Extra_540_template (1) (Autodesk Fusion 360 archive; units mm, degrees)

design "Extra_540_template" references "Extra_540_rear_tags"
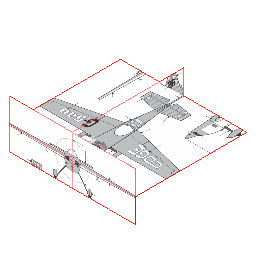
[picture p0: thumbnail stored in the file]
canvas "Canvas1"
canvas "Canvas2"
canvas "Canvas3"
component_insert "Component Insert"
ground "Ground4"

design "Extra_540_freeform_Undercarriage"
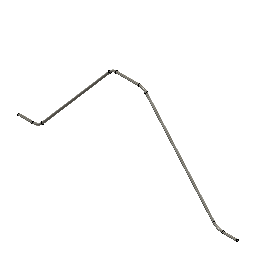
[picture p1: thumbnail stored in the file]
base_feature "Base Feature"
sketch "Path (1)" plane through (0, 0, -48.1) normal (0, 0, 1) x axis (1, 0, 0)
  dimension "d165" = 5
  dimension "d166" = 4
  dimension "d178" = 0
  dimension "d179" = 0
  dimension "d180" = 0
  dimension "d181" = 0
  dimension "d190" = 0
  dimension "d191" = 0
  dimension "d192" = 0
  dimension "d193" = 0
sketch "Profile" plane through (0, 0, 0) normal (1, 0, 0) x axis (0, 0, -1)
  circle C1 centre (47.7, -10.2807) radius 0.375
  dimension "d167" diameter C1 = 0.75
sweep "Sweep1" sketch "Profile" TwistAngle 0 TaperAngle 0

design "Propeller_3_x_1"
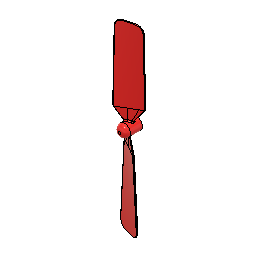
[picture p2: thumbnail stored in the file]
sketch "Sketch1" plane through (0, 0, 0) normal (1, 0, 0) x axis (0, 0, -1)
  dimension "d1" = 1
  dimension "d2" = 2.5
  dimension "d3" = 2
  dimension "d5" = 7
  dimension "d6" = 115
  dimension "d7" = 1.5
revolve "Revolve1" sketch "Sketch1" AlongAngle 360
work_plane "WorkPlane1" AlongDistance 38
sketch "Sketch2" plane through (0, 38, 0) normal (0, 1, 0) x axis (1, 0, 0)
  dimension "d10" = 3
  dimension "d11" = 10
  dimension "d12" = 0.5
  dimension "d13" = 10
work_plane "WorkPlane2" AlongDistance 7
sketch "Sketch3" plane through (0, 7, 0) normal (0, 1, 0) x axis (1, 0, 0)
  dimension "d15" = 10
  dimension "d16" = 0.5
  dimension "d17" = 30
sketch "Sketch4" plane through (0, 0, 0) normal (1, 0, 0) x axis (0, 0, -1)
sweep "Sweep1" sketch "Sketch3" TwistAngle -15 TaperAngle 0
sketch "Sketch5" plane through (0, 0, 0) normal (0, 1, 0) x axis (1, 0, 0)
  dimension "d24" = 0.5
  dimension "d25" = 1
  dimension "d26" = 60
sketch "Sketch6" plane through (0, 0, 0) normal (1, 0, 0) x axis (0, 0, -1)
loft "Loft2" sketch "Sketch5" + "Sketch3"
fillet "Fillet2" radius 3
fillet "Fillet3" radius 2
fillet "Fillet4" radius 0.2
fillet "Fillet5" radius 0.5
circular_pattern "C-Pattern1" TotalAngle 360

design "Extra_540_rear_tags" references "Extra_540_freeform_Undercarriage", "Motor_prop_rear_tags", "Sleeve", "Extra_540_wheel"
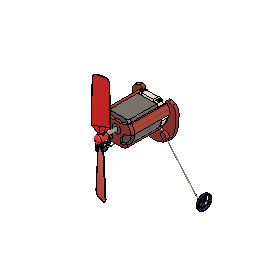
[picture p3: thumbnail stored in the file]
canvas "Canvas1"
canvas "Canvas2"
canvas "Canvas3"
component_insert "Component Insert4"
position "Position2"
base_feature "Base Feature"
work_plane "WorkPlane1" AlongDistance -50.1
sketch "Sketch3" plane through (0, 0, -50.1) normal (0, 0, 1) x axis (1, 0, 0)
extrude "Extrude1" new body sketch "Sketch3" along normal blind 2 taper -5
sketch "Sketch12" plane through (0, 0, -48.1) normal (0, 0, 1) x axis (1, 0, 0)
extrude "Extrude9" cut sketch "Sketch12" no distance stored
sketch "Sketch13" plane through (0, 0, -48.1) normal (0, 0, 1) x axis (1, 0, 0)
  dimension "d100" = 2
  dimension "d104" = 1.5
  dimension "d105" = 6
  dimension "d106" = 12
extrude "Extrude10" add sketch "Sketch13" along normal blind 25
sketch "Sketch14" plane through (0, 0, -23.1) normal (0, 0, 1) x axis (1, 0, 0)
  dimension "d109" = 6.0836
  dimension "d110" = 10
extrude "Extrude11" add sketch "Sketch14" along normal blind 1.5
sketch "Sketch7" plane through (0, 0, -48.1) normal (0, 0, 1) x axis (1, 0, 0)
  dimension "d141" = 4
  dimension "d143" = 4
  dimension "d144" = 2.5
  dimension "d113" = 2
  dimension "d114" = 8
extrude "Extrude5" add sketch "Sketch7" along normal blind 2.5
fillet "Fillet2" radius 1
sketch "Sketch8" plane through (4.0871, 0, 0) normal (1, 0, 0) x axis (0, 0, -1)
sketch "Sketch9" plane through (4.0871, 0, 0) normal (1, 0, 0) x axis (0, 0, -1)
  dimension "d148" = 0.4
  dimension "d149" = 0.8
extrude "Extrude6" cut sketch "Sketch9" to an object
sketch "Sketch10" plane through (0, 0, -48.1) normal (0, 0, 1) x axis (1, 0, 0)
  dimension "d154" = 29.9506
  dimension "d155" = 26.0609
  dimension "d161" = 2.5
  dimension "d162" = 3.5
extrude "Extrude7" add sketch "Sketch10" along normal blind 0.8
sketch "Sketch11" plane through (0, 0, -47.3) normal (0, 0, 1) x axis (1, 0, 0)
  dimension "d164" = 1
extrude "Extrude8" add sketch "Sketch11" along normal blind 1.5
fillet "Fillet3" radius 2
chamfer "Chamfer2" distance 0.5
fillet "Fillet4" radius 1.5
joint "Assemble11" OffsetX 0 OffsetY 0 OffsetZ 0 AngleZ 0 alignAngle 180 alignOffsetX 0 alignOffsetY 0 alignOffsetZ 0
ground "Ground7"
component_insert "Component Insert13"
joint "Assemble12" OffsetX 0 OffsetY 0 OffsetZ 0 AngleZ 0 alignAngle 0 alignOffsetX 0 alignOffsetY 0 alignOffsetZ 0
component_insert "Component Insert14"
joint "Assemble13" OffsetX 0 OffsetY 0 OffsetZ 0 AngleZ 0 OffsetX 0 OffsetY 0 OffsetZ 0 AngleZ 0 alignAngle -90 alignOffsetX 0 alignOffsetY 0 alignOffsetZ 0
component_insert "Component Insert15"
joint "Assemble14" OffsetX 0 OffsetY 0 OffsetZ 0 AngleZ 0 OffsetX 0 OffsetY 0 OffsetZ 0 AngleZ 0 alignAngle -90 alignOffsetX 0 alignOffsetY 0 alignOffsetZ 0
component_insert "Component Insert16"
component_insert "Component Insert17"
joint "Assemble15" OffsetX 0 OffsetY 0 OffsetZ 0 AngleZ 0 OffsetX 0 OffsetY 0 OffsetZ 0 AngleZ 0 alignAngle -90 alignOffsetX 0 alignOffsetY 0 alignOffsetZ 0
joint "Assemble16" OffsetX 0 OffsetY 0 OffsetZ 0 AngleZ 0 OffsetX 0 OffsetY 0 OffsetZ 0 AngleZ 0 alignAngle -90 alignOffsetX 0 alignOffsetY 0 alignOffsetZ 0
component_insert "Component Insert18"
joint "Assemble17" OffsetX 0 OffsetY 0 OffsetZ 0 AngleZ 0 OffsetX 0 OffsetY 0 OffsetZ 0 AngleZ 0 alignAngle 0 alignOffsetX 0 alignOffsetY 0 alignOffsetZ 0
component_insert "Component Insert19"
joint "Assemble18" OffsetX 0 OffsetY 0 OffsetZ 0 AngleZ 0 OffsetX 0 OffsetY 0 OffsetZ 0 AngleZ 0 alignAngle 0 alignOffsetX 0 alignOffsetY 0 alignOffsetZ 0
component_insert "Component Insert6"
joint "Assemble1" OffsetX 0 OffsetY 0 OffsetZ 0 AngleZ 0 alignAngle 0 alignOffsetX 0 alignOffsetY 0 alignOffsetZ 0
joint "Assemble2" OffsetX 0 OffsetY 0 OffsetZ 0 AngleZ 0 alignAngle 0 alignOffsetX 0 alignOffsetY 0 alignOffsetZ 0
component_insert "Component Insert7"
joint "Assemble3" OffsetX 0 OffsetY 0 OffsetZ 0 AngleZ 0 OffsetX 0 OffsetY 0 OffsetZ 0 AngleZ 0 alignAngle -90 alignOffsetX 0 alignOffsetY 0 alignOffsetZ 0
component_insert "Component Insert8"
joint "Assemble4" OffsetX 0 OffsetY 0 OffsetZ 0 AngleZ 0 OffsetX 0 OffsetY 0 OffsetZ 0 AngleZ 0 alignAngle 0 alignOffsetX 0 alignOffsetY 0 alignOffsetZ 0
component_insert "Component Insert9"
joint "Assemble5" OffsetX 0 OffsetY 0 OffsetZ 0 AngleZ 0 OffsetX 0 OffsetY 0 OffsetZ 0 AngleZ 0 alignAngle -90 alignOffsetX 0 alignOffsetY 0 alignOffsetZ 0
component_insert "Component Insert10"
joint "Assemble6" OffsetX 0 OffsetY 0 OffsetZ 0 AngleZ 0 OffsetX 0 OffsetY 0 OffsetZ 0 AngleZ 0 alignAngle -90 alignOffsetX 0 alignOffsetY 0 alignOffsetZ 0
component_insert "Component Insert11"
joint "Assemble7" OffsetX 0 OffsetY 0 OffsetZ 0 AngleZ 0 OffsetX 0 OffsetY 0 OffsetZ 0 AngleZ 0 alignAngle -90 alignOffsetX 0 alignOffsetY 0 alignOffsetZ 0
component_insert "Component Insert12"
joint "Assemble8" OffsetX 0 OffsetY 0 OffsetZ 0 AngleZ 0 OffsetX 0 OffsetY 0 OffsetZ 0 AngleZ 0 alignAngle 0 alignOffsetX 0 alignOffsetY 0 alignOffsetZ 0
ground "Ground4"
ground "Ground5"
position "Position3"
ground "Ground6"
joint "Assemble9" OffsetX 0 OffsetY 0 OffsetZ 0 AngleZ 0 alignAngle 180 alignOffsetX 0 alignOffsetY 0 alignOffsetZ 0
joint "Assemble10" OffsetX 0 OffsetY 0 OffsetZ 0 AngleZ 0 alignAngle 180 alignOffsetX 0 alignOffsetY 0 alignOffsetZ 0
ground "Ground3"
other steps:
create_component "CreateComponent3"
joint_origin "JointOrigin1" OffsetX 0 OffsetY 0 OffsetZ 0 AngleZ 0
joint_origin "JointOrigin2" OffsetX 0 OffsetY 0 OffsetZ 0 AngleZ 0
joint_origin "JointOrigin3" OffsetX 0 OffsetY 0 OffsetZ 0 AngleZ 0
joint_origin "JointOrigin4" OffsetX 0 OffsetY 0 OffsetZ 0 AngleZ 0
joint_origin "JointOrigin5" OffsetX 0 OffsetY 0 OffsetZ 0 AngleZ 0
joint_origin "JointOrigin6" OffsetX 0 OffsetY 0 OffsetZ 0 AngleZ 0

design "Motor_body_rev"
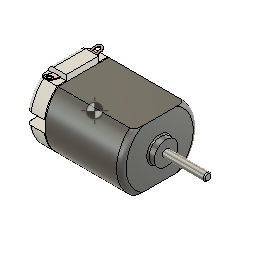
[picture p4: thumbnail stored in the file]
sketch "Sketch1" plane through (0, 0, 0) normal (1, 0, 0) x axis (0, 0, -1)
  dimension "d1" = 20.1
  dimension "d2" = 15.1
extrude "Extrude1" new body sketch "Sketch1" along normal blind 20
sketch "Sketch2" plane through (0, 0, 0) normal (-1, 0, 0) x axis (0, 0, 1)
  dimension "d5" = 1
extrude "Extrude2" add sketch "Sketch2" along normal blind 0.25
sketch "Sketch1"
sketch "Sketch2" plane through (0, 0, 0) normal (1, 0, 0) x axis (0, 0, -1)
work_plane "WorkPlane1"
sketch "Sketch3" plane through (-0.25, 6.55, 6.245) normal (1, 0, 0) x axis (0, 0, -1)
  dimension "d8" = 8.5
  dimension "d9" = 1.4
extrude "Extrude1" new body sketch "Sketch3" against normal blind 4.75
sketch "Sketch4" plane through (-5, 0, 0) normal (-1, 0, 0) x axis (0, 0, 1)
  dimension "d12" = 10
  dimension "d13" = 4
extrude "Extrude2" add sketch "Sketch4" along normal blind 2.3
sketch "Sketch3" plane through (20, 0, 0) normal (1, 0, 0) x axis (0, 0, -1)
  dimension "d16" = 6.15
extrude "Extrude3" add sketch "Sketch3" along normal blind 1.7
sketch "Sketch1" plane through (-7.3, 0, 0) normal (-1, 0, 0) x axis (0, 0, 1)
  dimension "d19" = 2
extrude "Extrude1" new body sketch "Sketch1" along normal blind 2
sketch "Sketch2" plane through (21.7, 0, 0) normal (1, 0, 0) x axis (0, 0, -1)
  circle C1 centre (0, 0) radius 3.075
extrude "Extrude4" cut of existing geometry blind -38
work_plane "WorkPlane1" AlongDistance 2
sketch "Sketch1" plane through (-2, 0, 0) normal (-1, 0, 0) x axis (0, 0, -1)
  dimension "d29" = 3.25
  dimension "d30" = 0.2
  dimension "d31" = 15
extrude "Extrude1" new body sketch "Sketch1" along normal blind 2
fillet "Fillet1" radius 1
sketch "Sketch2" plane through (0, 6.4116, 1.718) normal (0, 0.9659, 0.2588) x axis (1, 0, 0)
  dimension "d36" = 1.5
  dimension "d37" = 0.5
extrude "Extrude2" cut sketch "Sketch2" to an object
sketch "Sketch3" plane through (0, 6.4116, -1.718) normal (0, 0.9659, -0.2588) x axis (-1, 0, 0)
  dimension "d41" = 1.5
  dimension "d42" = 0.5
extrude "Extrude3" cut sketch "Sketch3" to an object
sketch "Sketch5" plane through (-5, 0, 0) normal (-1, 0, 0) x axis (0, 0, 1)
  dimension "d45" = 6
  dimension "d46" = 1
  dimension "d47" = 1
  dimension "d48" = 7
extrude "Extrude4" add sketch "Sketch5" along normal blind 0.1
sketch "Sketch6" plane through (-5, 0, 0) normal (-1, 0, 0) x axis (0, 0, 1)
  dimension "d51" = 3
  dimension "d52" = 4.825
extrude "Extrude5" cut sketch "Sketch6" to an object
fillet "Fillet1" radius 1.25
fillet "Fillet1" radius 1.25
extrude "Extrude3" add of existing geometry blind 40
chamfer "Chamfer1" distance 0.5 rotateAngle 45
fillet "Fillet2" radius 1.4
fillet "Fillet2" radius 0.3
fillet "Fillet1" radius 0.25
ground "Ground1"
joint "Assemble1" alignAngle 0 alignOffsetX 0 alignOffsetY 0 alignOffsetZ 11
move "Move1"
ground "Ground2"
ground "Ground3"
component_from_bodies "Body->Comp"
joint "Assemble5" alignAngle 0 alignOffsetX 0 alignOffsetY 0 alignOffsetZ 0
joint "Assemble6" alignAngle 0 alignOffsetX 0 alignOffsetY 0 alignOffsetZ 0
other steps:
base_feature "Base Feature"
create_component "CreateComponent1"
create_component "CreateComponent2"
extrude "Extrude3" cut of existing geometry blind -38
extrude "Extrude2" cut of existing geometry blind -38
create_component "CreateComponent3"
joint_origin "JointOrigin1" OffsetX 0 OffsetY 0 OffsetZ 0 AngleZ 0
joint_origin "JointOrigin1" OffsetX 0 OffsetY 0 OffsetZ 0 AngleZ 0
create_component "CreateComponent4"
remove_body "RemoveBody1"
joint_origin "JointOrigin3" OffsetX 0 OffsetY 0 OffsetZ 0 AngleZ 0
joint_origin "JointOrigin4" OffsetX 0 OffsetY 0 OffsetZ 0 AngleZ 0
joint_origin "JointOrigin2" OffsetX 0 OffsetY 0 OffsetZ 0 AngleZ 0
joint_origin "JointOrigin5" OffsetX 0 OffsetY 0 OffsetZ 0 AngleZ 0

design "Sleeve"
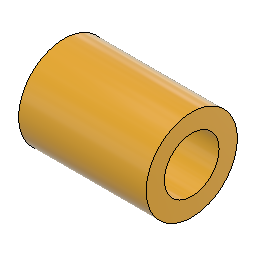
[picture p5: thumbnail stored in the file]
sketch "Sketch1" plane through (0, 0, 0) normal (1, 0, 0) x axis (0, 0, -1)
  circle C1 centre (0, 0) radius 0.375
  circle C2 centre (0, 0) radius 0.625
  dimension "d1" diameter C1 = 0.75
  dimension "d2" diameter C2 = 1.25
extrude "Extrude1" new body sketch "Sketch1" along normal blind 1.75

design "Extra_540_wheel"
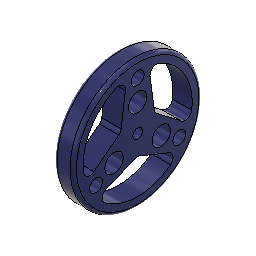
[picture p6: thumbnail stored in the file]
sketch "Sketch1" plane through (0, 0, 0) normal (1, 0, 0) x axis (0, 0, -1)
  dimension "d1" = 0.75
  dimension "d2" = 10
  dimension "d5" = 1
  dimension "d6" = 0.4
  dimension "d7" = 2
extrude "Extrude1" new body sketch "Sketch1" along normal blind 1.5
fillet "Fillet1" radius 0.5
fillet "Fillet2" radius 0.25

design "Motor_prop_rear_tags" references "Propeller_3_x_1", "Motor_body_rev"
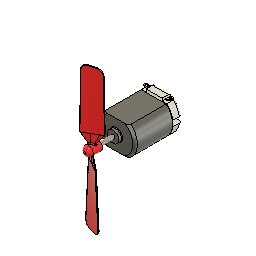
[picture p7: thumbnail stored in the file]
component_insert "Component Insert1"
ground "Ground1"
component_insert "Component Insert2"
joint "Assemble1" OffsetX 0 OffsetY 0 OffsetZ 0 AngleZ 0 OffsetX 0 OffsetY 0 OffsetZ 0 AngleZ 0 alignAngle 180 alignOffsetX 0 alignOffsetY 0 alignOffsetZ 3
